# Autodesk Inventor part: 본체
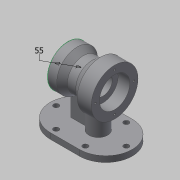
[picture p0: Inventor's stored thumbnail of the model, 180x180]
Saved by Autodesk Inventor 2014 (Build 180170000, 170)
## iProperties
Created: 2020-01
Part Number: 본체
Material: Generic
Document SubType Name: Modeling
Designer: kh
Density: 1 g/cm^3
Appearance: Default
Author: kh
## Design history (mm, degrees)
sketch "Sketch1"
  geometry: L1 (-25, 0)-(25, 0); L2 (-25, -45)-(25, -45); L3 (25, 45)-(-25, 45); A1 r 45 centre (-25, 0) between (-25, 45) and (-25, -45); A2 r 45 centre (25, 0) between (25, -45) and (25, 45); 2 further points
  constraints: 8 end point, 4 point on circle, 4 tangent, 2 centre point, 1 coincident, 1 horizontal, 1 midpoint, 1 parallel
  dimensions: "d0" = 45 radius of A1; "d1" = 50 distance of L3.start L3.end
extrude "Extrusion1" new body sketch "Sketch1" distance "d2" = 10; taper "d3" = 0 deg
sketch "Sketch2"
  geometry: L1 (-25, -45)-(25, -45) reference; L2 (25, 45)-(-25, 45) reference; L3 (25, -35)-(-25, -35); L4 (-25, 35)-(25, 35); A1 r 45 centre (25, 0) between (25, -45) and (25, 45) reference; A2 r 45 centre (-25, 0) between (-25, 45) and (-25, -45) reference; A3 r 35 centre (25, 0) between (25, -35) and (25, 35); A4 r 35 centre (-25, 0) between (-25, 35) and (-25, -35); 4 further points
  constraints: 5 point on circle, 4 end point, 2 centre point, 2 coincident, 3 other
  dimensions: "d4" = 10 distance between parallel lines of L2 L4
hole "Hole1" sketch "Sketch2" diameter "d5" = 9; stored, may be unused: countersink angle "d9" = 90 deg, drill point angle "d11" = 118 deg; dims "d6" = 6, "d7" = 4, "d8" = 2, "d10" = 8
mirror "Mirror1"
hole "Hole2" sketch "Sketch2" diameter "d12" = 9; stored, may be unused: countersink angle "d16" = 90 deg, drill point angle "d18" = 118 deg; dims "d13" = 6, "d14" = 4, "d15" = 2, "d17" = 8
mirror "Mirror2"
sketch "Sketch3"
  geometry: L1 (-40, 80)-(40, 80); L2 (70, 0)-(25, 0) reference; L3 (-70, 0)-(-70, 10) reference; L4 (-40, 80)-(-40, 120); L5 (-40, 120)-(-16, 120); L6 (-16, 120)-(-1.103, 107.5); L7 (-1.103, 107.5)-(13.289, 107.5); L8 (13.289, 107.5)-(24, 115); L9 (24, 115)-(40, 115); L10 (40, 115)-(40, 80); 1 further point
  constraints: 16 end point, 4 parallel, 1 horizontal, 1 perpendicular
  dimensions: "d19" = 80 distance from line of L2 L1.end; "d20" = 80 distance of L1.start L1.end; "d21" = 30 horizontal distance of L3.start L1.start; "d22" = 80 diameter of L5 L1; "d23" = 24 distance of L4.end L5.end; "d24" = 55 diameter of L7 L1; "d25" = 16 distance of L8.end L9.end; "d26" = 70 diameter of L9 L1; "d27" = 35 deg angle of L7 L8; "d28" = 40 deg angle of L7 L6
revolve "Revolution1" sketch "Sketch3" stored, may be unused: angle "d29" = 90 deg
sketch "Sketch4"
  geometry: L1 (25, 45)-(-25, 45) reference; L2 (70, 0)-(70, -24.272); C1 r 16 at (12, 0); A1 r 45 centre (25, 0) between (25, -45) and (25, 45) reference; A2 r 45 centre (25, 0) between (25, -45) and (25, 45) reference; 1 further point
  constraints: 2 end point, 2 tangent, 1 centre point, 1 horizontal alignment, 1 perpendicular, 1 point on circle
  dimensions: "d30" = 16 radius of C1; "d31" = 58 distance of C1.centre L2.start
extrude "Extrusion2" join sketch "Sketch4" distance "d32" = 77; taper "d33" = 0 deg
sketch "Sketch5"
  geometry: L1 (30, 45)-(30, 10); L2 (24, 45)-(40, 45) reference; L3 (70, 10)-(25, 10) reference; L4 (40, 45)-(40, 115) reference; 1 further point
  constraints: 2 end point, 2 point on line, 1 vertical
  dimensions: "d34" = 10 distance between parallel lines of L1 L4
feature "Rib1" sketch "Sketch5" dims "d35" = 1, "d36" = 10, "d37" = 0, "d38" = 0, "d39" = 1, "d40" = 1
hole "Hole3" diameter "d43" = 32; stored, may be unused: countersink angle "d47" = 90 deg, drill point angle "d49" = 118 deg; dims "d41" = 10, "d42" = 10, "d44" = 6, "d45" = 52, "d46" = 20, "d48" = 8
hole "Hole4" diameter "d52" = 40; stored, may be unused: countersink angle "d56" = 90 deg, drill point angle "d58" = 118 deg; dims "d50" = 10, "d51" = 10, "d53" = 6, "d54" = 52, "d55" = 20, "d57" = 17
sketch "Sketch7" dims "d59" = 66
  geometry: C1 r 26 at (0, 0) reference; C2 r 40 at (0, 0) reference; 3 further points
  constraints: 2 horizontal alignment, 1 coincident, 2 other
hole "Hole5" sketch "Sketch7" at (-33, 0) diameter "d60" = 3.242; stored, may be unused: countersink angle "d64" = 90 deg, drill point angle "d66" = 118 deg; dims "d61" = 9, "d62" = 52, "d63" = 20, "d65" = 11
pattern_circular "Circular Pattern1" dims angle "d68" = 360 deg
sketch "Sketch8" dims "d70" = 55
  geometry: C1 r 20 at (0, 0) reference; C2 r 35 at (0, 0) reference; 3 further points
  constraints: 2 horizontal alignment, 1 coincident, 2 other
body "Solid1"
